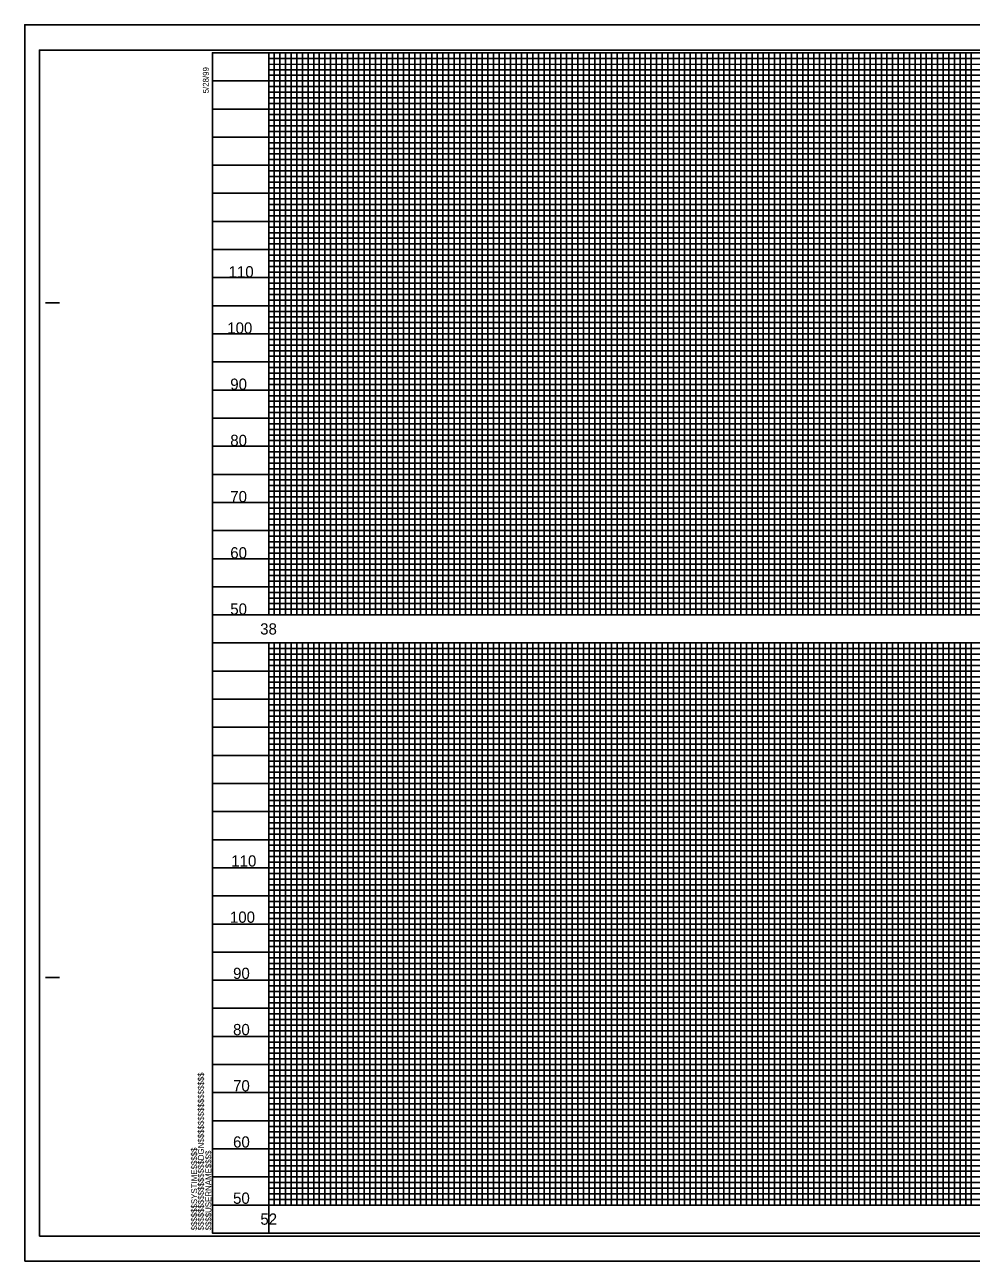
# Model space of a CAD drawing. Extents: x 2367101 to 2368930, y 803279 to 808979.
# Drawn here: x 2367101 to 2367943, y 803279 to 804379 of the extents above; entities that cross this region are included whole.
import ezdxf

# ---------------------------------------------------------------- set-up
doc = ezdxf.new("R2010")
doc.units = 0
for name, color, linetype in [('Old_Level_11', 7, 'Continuous'), ('Old_Level_12', 7, 'Continuous'), ('Old_Level_13', 7, 'Continuous'), ('Old_Level_14', 7, 'Continuous'), ('Old_Level_15', 7, 'Continuous'), ('Old_Level_17', 7, 'Continuous'), ('Old_Level_19', 7, 'Continuous'), ('Old_Level_4', 7, 'Continuous'), ('Old_Level_5', 7, 'Continuous'), ('Old_Level_6', 7, 'Continuous'), ('Old_Level_63', 7, 'Continuous'), ('Old_Level_8', 7, 'Continuous'), ('Old_Level_9', 7, 'Continuous')]:
    doc.layers.add(name, color=color, linetype=linetype)

msp = doc.modelspace()

# ---------------------------------------------------------------- linework, layer by layer
at = {"layer": 'Old_Level_11'}
for p, q in [((2367768, 803829), (2367818, 803829)), ((2367868, 803829), (2367918, 803829)), ((2367268, 803329), (2367268, 803329))]:
    msp.add_line(p, q, dxfattribs=at)
for points in [[(2367318, 804354), (2367318, 803854), (2367368, 803854), (2367368, 804354), (2367418, 804354), (2367418, 803854), (2367468, 803854), (2367468, 804354), (2367518, 804354), (2367518, 803854), (2367568, 803854), (2367568, 804354), (2367618, 804354), (2367618, 803854), (2367668, 803854), (2367668, 804354), (2367718, 804354), (2367718, 803854), (2367768, 803854), (2367768, 804354), (2367818, 804354), (2367818, 803854), (2367868, 803854), (2367868, 804354), (2367918, 804354), (2367918, 803854), (2367968, 803854)], [(2367268, 804304), (2368568, 804304)], [(2368568, 804254), (2367268, 804254), (2367268, 804204), (2368568, 804204)], [(2368768, 804154), (2367268, 804154), (2367268, 804104), (2368768, 804104)], [(2368768, 804054), (2367268, 804054), (2367268, 804004), (2368768, 804004)], [(2368768, 803954), (2367268, 803954), (2367268, 803954), (2367268, 803904), (2368768, 803904)], [(2367318, 803829), (2367318, 803329), (2367368, 803329), (2367368, 803829), (2367418, 803829), (2367418, 803329), (2367468, 803329), (2367468, 803829), (2367518, 803829), (2367518, 803329), (2367568, 803329), (2367568, 803829), (2367618, 803829), (2367618, 803329), (2367668, 803329), (2367668, 803829), (2367718, 803829), (2367718, 803329), (2367768, 803329), (2367768, 803829), (2367818, 803829), (2367818, 803329), (2367868, 803329), (2367868, 803829), (2367918, 803829), (2367918, 803329), (2367968, 803329)], [(2368768, 803779), (2367268, 803779)], [(2368768, 803729), (2367268, 803729), (2367268, 803679), (2368768, 803679)], [(2368768, 803629), (2367268, 803629), (2367268, 803579), (2368768, 803579)], [(2368768, 803529), (2367268, 803529), (2367268, 803479), (2368768, 803479)], [(2368768, 803429), (2367268, 803429), (2367268, 803429), (2367268, 803379), (2368768, 803379)], [(2368768, 803329), (2367268, 803329)]]:
    msp.add_lwpolyline(points, dxfattribs=at)
at = {"layer": 'Old_Level_12'}
msp.add_line((2367268, 804329), (2368567.9, 804329), dxfattribs=at)
for points in [[(2367343, 804354), (2367343, 803854), (2367393, 803854), (2367393, 804354), (2367443, 804354), (2367443, 803854), (2367493, 803854), (2367493, 804354), (2367543, 804354), (2367543, 803854), (2367593, 803854), (2367593, 804354), (2367643, 804354), (2367643, 803854), (2367693, 803854), (2367693, 804354), (2367743, 804354), (2367743, 803854), (2367793, 803854), (2367793, 804354), (2367843, 804354), (2367843, 803854), (2367893, 803854), (2367893, 803854), (2367893, 804354), (2367943, 804354), (2367943, 803854), (2367993, 803854)], [(2368568, 804279), (2367268, 804279), (2367268, 804229), (2368568, 804229)], [(2368768, 804179), (2367268, 804179), (2367268, 804129), (2368593, 804129)], [(2368768, 804079), (2367268, 804079), (2367268, 804029), (2368768, 804029)], [(2368768, 803979), (2367268, 803979), (2367268, 803929), (2368768, 803929)], [(2368768, 803879), (2367268, 803879)], [(2367293, 803829), (2367343, 803829), (2367343, 803329), (2367393, 803329), (2367393, 803829), (2367443, 803829), (2367443, 803329), (2367493, 803329), (2367493, 803829), (2367543, 803829), (2367543, 803329), (2367593, 803329), (2367593, 803829), (2367643, 803829), (2367643, 803329), (2367693, 803329), (2367693, 803829), (2367743, 803829), (2367743, 803329), (2367793, 803329), (2367793, 803829), (2367843, 803829), (2367843, 803329), (2367893, 803329), (2367893, 803329), (2367893, 803829), (2367943, 803829), (2367943, 803329), (2367993, 803329)], [(2367268, 803804), (2368768, 803804)], [(2368768, 803754), (2367268, 803754), (2367268, 803704), (2368768, 803704)], [(2368768, 803654), (2367268, 803654), (2367268, 803604), (2368768, 803604)], [(2368768, 803554), (2367268, 803554), (2367268, 803504), (2368768, 803504)], [(2368768, 803454), (2367268, 803454), (2367268, 803404), (2368768, 803404)], [(2368768, 803354), (2367268, 803354)]]:
    msp.add_lwpolyline(points, dxfattribs=at)
at = {"layer": 'Old_Level_13'}
for p, q in [((2367318, 803854), (2367318, 804354)), ((2367368, 803854), (2367368, 804354)), ((2367418, 803854), (2367418, 804354)), ((2367468, 803854), (2367468, 804354)), ((2367518, 803854), (2367518, 804354)), ((2367568, 803854), (2367568, 804354)), ((2367618, 803854), (2367618, 804354)), ((2367668, 803854), (2367668, 804354)), ((2367718, 803854), (2367718, 804354)), ((2367768, 803854), (2367768, 804354)), ((2367818, 803854), (2367818, 804354)), ((2367868, 803854), (2367868, 804354)), ((2367918, 803854), (2367918, 804354)), ((2368567.9, 804304), (2367268, 804304)), ((2368567.9, 804254), (2367268, 804254)), ((2368568, 804204), (2367268, 804204)), ((2368768, 804154), (2367268, 804154)), ((2368768, 804104), (2367268, 804104)), ((2368768, 804054), (2367268, 804054)), ((2368768, 804004), (2367268, 804004)), ((2368768, 803954), (2367268, 803954)), ((2368768, 803904), (2367268, 803904)), ((2367268, 803829), (2368767.9, 803829)), ((2367318, 803829), (2367318, 803329)), ((2367368, 803829), (2367368, 803329)), ((2367418, 803829), (2367418, 803329)), ((2367468, 803829), (2367468, 803329)), ((2367518, 803829), (2367518, 803329)), ((2367568, 803829), (2367568, 803329)), ((2367618, 803829), (2367618, 803329)), ((2367668, 803829), (2367668, 803329)), ((2367718, 803829), (2367718, 803329)), ((2367768, 803829), (2367768, 803329)), ((2367818, 803829), (2367818, 803329)), ((2367868, 803829), (2367868, 803329)), ((2367918, 803829), (2367918, 803329)), ((2367268, 803779), (2368767.9, 803779)), ((2367268, 803729), (2368767.9, 803729)), ((2367268, 803679), (2368767.9, 803679)), ((2367268, 803629), (2368767.9, 803629)), ((2367268, 803579), (2368767.9, 803579)), ((2367268, 803529), (2368767.9, 803529)), ((2367268, 803479), (2368767.9, 803479)), ((2367268, 803429), (2368767.9, 803429)), ((2367268, 803379), (2368767.9, 803379))]:
    msp.add_line(p, q, dxfattribs=at)
at = {"layer": 'Old_Level_14'}
msp.add_line((2367318, 803329), (2367318, 803304), dxfattribs=at)
at = {"layer": 'Old_Level_15'}
for p, q in [((2368785, 804379), (2367101, 804379)), ((2367101, 804379), (2367101, 803279)), ((2367101, 803279), (2368785, 803279))]:
    msp.add_line(p, q, dxfattribs=at)
at = {"layer": 'Old_Level_19'}
msp.add_line((2367268, 803904), (2367268, 803904), dxfattribs=at)
at = {"layer": 'Old_Level_4'}
msp.add_lwpolyline([(2367114, 803301.4), (2368780.5, 803301.4), (2368780.5, 804356.5), (2367114, 804356.5)], close=True, dxfattribs=at)
at = {"layer": 'Old_Level_5'}
msp.add_lwpolyline([(2367318, 803829), (2368718, 803829), (2368718, 803329), (2367318, 803329)], close=True, dxfattribs=at)
at = {"layer": 'Old_Level_6'}
msp.add_lwpolyline([(2367101, 803279), (2368785, 803279), (2368785, 804379), (2367101, 804379)], close=True, dxfattribs=at)
at = {"layer": 'Old_Level_63'}
msp.add_lwpolyline([(2367318, 804192.9), (2367318, 803854), (2368718, 803854), (2368718, 804192.9)], dxfattribs=at)
at = {"layer": 'Old_Level_8'}
for p, q in [((2367318, 804349), (2368568, 804349)), ((2367318, 804344), (2367318, 804344)), ((2368568, 804344), (2367318, 804343.6)), ((2367318, 804339), (2368568, 804339)), ((2368567.9, 804219), (2367318, 804219)), ((2368568, 804214), (2367318, 804214)), ((2368568, 804209), (2367318, 804209)), ((2367318, 804199), (2368568, 804199)), ((2368568, 804194), (2367318, 804194)), ((2367318, 804189), (2368718, 804189)), ((2368718, 804169), (2367318, 804169)), ((2367318, 804164), (2368718, 804164)), ((2368718, 804144), (2367318, 804144)), ((2367318, 804139), (2368718, 804139)), ((2368718, 804119), (2367318, 804119)), ((2367318, 804114), (2368718, 804114)), ((2368718, 804109), (2367318, 804109)), ((2367318, 804099), (2368718, 804099)), ((2368718, 804094), (2367318, 804094)), ((2367318, 804089), (2368718, 804089)), ((2368718, 804084), (2367318, 804084)), ((2367318, 804074), (2368718, 804074)), ((2368718, 804069), (2367318, 804069)), ((2367318, 804064), (2368718, 804064)), ((2368718, 804059), (2367318, 804059)), ((2367318, 804049), (2368718, 804049)), ((2368718, 804044), (2367318, 804044)), ((2367318, 804039), (2368718, 804039)), ((2368718, 804034), (2367318, 804034)), ((2367318, 804024), (2368718, 804024)), ((2368718, 804019), (2367318, 804019)), ((2367318, 804014), (2368718, 804014)), ((2368718, 804009), (2367318, 804009)), ((2367318, 803999), (2368718, 803999)), ((2368718, 803994), (2367318, 803994)), ((2367318, 803989), (2368718, 803989)), ((2368718, 803984), (2367318, 803984)), ((2367318, 803974), (2368718, 803974)), ((2368718, 803969), (2367318, 803969)), ((2368718, 803964), (2367318, 803964)), ((2368718, 803959), (2367318, 803959)), ((2367318, 803949), (2368718, 803949)), ((2368718, 803944), (2367318, 803944)), ((2367318, 803939), (2368718, 803939)), ((2368718, 803934), (2367318, 803934)), ((2367318, 803924), (2368718, 803924)), ((2368718, 803919), (2367318, 803919)), ((2367318, 803914), (2368718, 803914)), ((2368718, 803909), (2367318, 803909)), ((2367318, 803899), (2368718, 803899)), ((2368718, 803894), (2367318, 803894)), ((2367318, 803889), (2368718, 803889)), ((2368718, 803884), (2367318, 803884)), ((2367318, 803874), (2368718, 803874)), ((2368718, 803869), (2367318, 803869)), ((2367318, 803864), (2368718, 803864)), ((2367318, 803824), (2368718, 803824)), ((2368718, 803819), (2367318, 803819)), ((2367318, 803814), (2368718, 803814)), ((2368718, 803809), (2367318, 803809)), ((2367318, 803799), (2368718, 803799)), ((2368718, 803794), (2367318, 803794)), ((2367318, 803789), (2368718, 803789)), ((2368718, 803784), (2367318, 803784)), ((2367318, 803774), (2368718, 803774)), ((2368718, 803769), (2367318, 803769)), ((2367318, 803764), (2368718, 803764)), ((2368718, 803759), (2367318, 803759)), ((2367318, 803749), (2368718, 803749)), ((2368718, 803744), (2367318, 803744)), ((2367318, 803739), (2368718, 803739)), ((2368718, 803734), (2367318, 803734)), ((2367318, 803724), (2368718, 803724)), ((2368718, 803719), (2367318, 803719)), ((2367318, 803714), (2368718, 803714)), ((2368718, 803709), (2367318, 803709)), ((2367318, 803699), (2368718, 803699)), ((2368718, 803694), (2367318, 803694)), ((2367318, 803689), (2368718, 803689)), ((2368718, 803684), (2367318, 803684)), ((2367318, 803674), (2368718, 803674)), ((2368718, 803669), (2367318, 803669)), ((2367318, 803664), (2368718, 803664)), ((2368718, 803659), (2367318, 803659)), ((2367318, 803649), (2368718, 803649)), ((2368718, 803644), (2367318, 803644)), ((2367318, 803639), (2368718, 803639)), ((2368718, 803634), (2367318, 803634.1)), ((2367318, 803624), (2368718, 803624)), ((2368718, 803619), (2367318, 803619)), ((2367318, 803614), (2368718, 803614)), ((2368718, 803609), (2367318, 803609)), ((2367318, 803599), (2368718, 803599)), ((2368718, 803594), (2367318, 803594)), ((2367318, 803589), (2368718, 803589)), ((2368718, 803584), (2367318, 803584)), ((2367318, 803574), (2368718, 803574)), ((2368718, 803569), (2367318, 803569)), ((2367318, 803564), (2368718, 803564)), ((2368718, 803559), (2367318, 803559)), ((2367318, 803549), (2368718, 803549)), ((2368718, 803544), (2367318, 803544)), ((2367318, 803539), (2368718, 803539)), ((2368718, 803534), (2367318, 803534)), ((2367318, 803524), (2368718, 803524)), ((2368718, 803519), (2367318, 803519)), ((2367318, 803514), (2368718, 803514)), ((2368718, 803509), (2367318, 803509)), ((2367318, 803499), (2368718, 803499)), ((2368718, 803494), (2367318, 803494)), ((2367318, 803489), (2368718, 803489)), ((2368718, 803484), (2367318, 803484)), ((2367318, 803474), (2368718, 803474)), ((2368718, 803469), (2367318, 803469)), ((2367318, 803464), (2368718, 803464)), ((2368718, 803459), (2367318, 803459)), ((2367318, 803449), (2368718, 803449)), ((2368718, 803444), (2367318, 803444)), ((2367318, 803439), (2368718, 803439)), ((2368718, 803434), (2367318, 803434)), ((2367318, 803424), (2368718, 803424)), ((2368718, 803419), (2367318, 803419)), ((2367318, 803414), (2368718, 803414)), ((2368718, 803409), (2367318, 803409)), ((2367318, 803399), (2368718, 803399)), ((2368718, 803394), (2367318, 803394)), ((2367318, 803389), (2368718, 803389)), ((2368718, 803384), (2367318, 803384)), ((2367318, 803374), (2368718, 803374)), ((2368718, 803369), (2367318, 803369)), ((2367318, 803364), (2368718, 803364)), ((2368718, 803359), (2367318, 803359)), ((2367318, 803349), (2368718, 803349)), ((2368718, 803344), (2367318, 803344)), ((2367318, 803339), (2368718, 803339)), ((2367318, 803334), (2368718, 803334))]:
    msp.add_line(p, q, dxfattribs=at)
for points in [[(2367323, 804354), (2367323, 803854), (2367328, 803854), (2367328, 804354), (2367333, 804354), (2367333, 803854), (2367338, 803854), (2367338, 804354), (2367348, 804354), (2367348, 803854), (2367353, 803854), (2367353, 804354), (2367358, 804354), (2367358, 803854), (2367363, 803854), (2367373, 803854), (2367378, 803854), (2367378, 804354), (2367383, 804354), (2367383, 803854), (2367388, 803854), (2367388, 804354), (2367398, 804354), (2367398, 803854), (2367403, 803854), (2367403, 804354), (2367408, 804354), (2367408, 803854), (2367413, 803854), (2367413, 804354), (2367423, 804354), (2367423, 803854), (2367428, 803854), (2367428, 804354), (2367433, 804354), (2367433, 803854), (2367438, 803854), (2367438, 804354), (2367448, 804354), (2367448, 803854), (2367453, 803854), (2367453, 804354), (2367458, 804354), (2367458, 803854), (2367463, 803854), (2367463, 804354), (2367473, 804354), (2367473, 803854), (2367478, 803854), (2367478, 804354), (2367483, 804354), (2367483, 803854), (2367488, 803854), (2367488, 804354), (2367498, 804354), (2367498, 803854), (2367503, 803854), (2367503, 804354), (2367508, 804354), (2367508, 803854), (2367513, 803854), (2367513, 804354), (2367523, 804354), (2367523, 803854), (2367528, 803854), (2367528, 804354), (2367533, 804354), (2367533, 803854)], [(2367363, 803854), (2367363, 804354), (2367373, 804354), (2367373, 803854)], [(2367533, 803854), (2367538, 803854), (2367538, 804354), (2367548, 804354), (2367548, 803854), (2367553, 803854), (2367553, 804354), (2367558, 804354), (2367558, 803854), (2367563, 803854), (2367563, 804354), (2367573, 804354), (2367573, 803854), (2367578, 803854), (2367578, 804354), (2367583, 804354), (2367583, 803854), (2367588, 803854), (2367588, 804354), (2367598, 804354), (2367598, 803854), (2367603, 803854), (2367603, 804354), (2367608, 804354), (2367608, 803854), (2367613, 803854), (2367613, 804354), (2367623, 804354), (2367623, 803854), (2367628, 803854), (2367628, 804354), (2367633, 804354), (2367633, 803854), (2367638, 803854), (2367638, 804354), (2367648, 804354), (2367648, 803854), (2367653, 803854), (2367653, 804354), (2367658, 804354), (2367658, 803854), (2367663, 803854), (2367663, 804354), (2367673, 804354), (2367673, 803854), (2367678, 803854), (2367678, 804354), (2367683, 804354), (2367683, 803854), (2367688, 803854), (2367688, 804354), (2367698, 804354), (2367698, 803854), (2367703, 803854), (2367703, 804354), (2367708, 804354), (2367708, 803854), (2367713, 803854), (2367713, 804354), (2367723, 804354), (2367723, 803854), (2367728, 803854), (2367728, 804354), (2367733, 804354), (2367733, 803854), (2367738, 803854), (2367738, 804354), (2367748, 804354), (2367748, 803854), (2367753, 803854), (2367753, 804354), (2367758, 804354), (2367758, 803854), (2367763, 803854), (2367763, 804354), (2367773, 804354), (2367773, 803854), (2367778, 803854), (2367778, 804354), (2367783, 804354), (2367783, 803854), (2367788, 803854), (2367788, 804354), (2367798, 804354), (2367798, 803854), (2367803, 803854), (2367803, 804354), (2367808, 804354), (2367808, 803854), (2367813, 803854), (2367813, 804354), (2367823, 804354), (2367823, 803854), (2367828, 803854), (2367828, 804354), (2367833, 804354), (2367833, 803854), (2367838, 803854), (2367838, 804354), (2367848, 804354)], [(2367848, 804354), (2367848, 803854), (2367853, 803854), (2367853, 804354), (2367858, 804354), (2367858, 803854), (2367863, 803854), (2367863, 804354), (2367873, 804354), (2367873, 803854), (2367878, 803854), (2367878, 804354), (2367883, 804354), (2367883, 803854), (2367888, 803854), (2367888, 804354), (2367898, 804354), (2367898, 803854), (2367903, 803854), (2367903, 804354), (2367908, 804354), (2367908, 803854), (2367913, 803854), (2367913, 804354), (2367923, 804354), (2367923, 803854), (2367928, 803854), (2367928, 804354), (2367933, 804354), (2367933, 803854), (2367938, 803854), (2367938, 804354), (2367948, 804354)], [(2368568, 804334), (2367318, 804334), (2367318, 804324), (2368568, 804324)], [(2368567.9, 804319), (2367318, 804319), (2367318, 804314), (2368568, 804314)], [(2368568, 804309), (2367318, 804309), (2367318, 804299), (2368568, 804299)], [(2368568, 804294), (2367318, 804294), (2367318, 804289), (2368568, 804289)], [(2368568, 804284), (2367318, 804284), (2367318, 804274), (2368568, 804274)], [(2368568, 804269), (2367318, 804269), (2367318, 804264), (2368568, 804264)], [(2368568, 804259), (2367318, 804259), (2367318, 804249), (2368568, 804249)], [(2368568, 804243.9), (2367318.1, 804243.9), (2367318.1, 804239), (2368568, 804239)], [(2368568, 804234), (2367318, 804234), (2367318, 804224), (2368568, 804224)], [(2368718, 804184), (2367318, 804184), (2367318, 804174), (2368718, 804174)], [(2368718, 804159), (2367318, 804159), (2367318, 804149), (2368718, 804149)], [(2368718, 804134), (2367318, 804134), (2367318, 804124), (2368718, 804124)], [(2368718, 803859), (2367318, 803859)], [(2367318, 803829), (2367323, 803829), (2367323, 803329), (2367328, 803329), (2367328, 803829), (2367333, 803829), (2367333, 803329), (2367338, 803329), (2367338, 803829), (2367348, 803829), (2367348, 803329), (2367353, 803329), (2367353, 803829), (2367358, 803829), (2367358, 803329), (2367363, 803329), (2367373, 803329), (2367378, 803329), (2367378, 803829), (2367383, 803829), (2367383, 803329), (2367388, 803329), (2367388, 803829), (2367398, 803829), (2367398, 803329), (2367403, 803329), (2367403, 803829), (2367408, 803829), (2367408, 803329), (2367413, 803329), (2367413, 803829), (2367423, 803829), (2367423, 803329), (2367428, 803329), (2367428, 803829), (2367433, 803829), (2367433, 803329), (2367438, 803329), (2367438, 803829), (2367448, 803829), (2367448, 803329), (2367453, 803329), (2367453, 803829), (2367458, 803829), (2367458, 803329), (2367463, 803329), (2367463, 803829), (2367473, 803829), (2367473, 803329), (2367478, 803329), (2367478, 803829), (2367483, 803829), (2367483, 803329), (2367488, 803329), (2367488, 803829), (2367498, 803829), (2367498, 803329), (2367503, 803329), (2367503, 803829), (2367508, 803829), (2367508, 803329), (2367513, 803329), (2367513, 803829), (2367523, 803829), (2367523, 803329), (2367528, 803329), (2367528, 803829), (2367533, 803829), (2367533, 803329)], [(2367363, 803329), (2367363, 803829), (2367373, 803829), (2367373, 803329)], [(2367533, 803329), (2367538, 803329), (2367538, 803829), (2367548, 803829), (2367548, 803329), (2367553, 803329), (2367553, 803829), (2367558, 803829), (2367558, 803329), (2367563, 803329), (2367563, 803829), (2367573, 803829), (2367573, 803329), (2367578, 803329), (2367578, 803829), (2367583, 803829), (2367583, 803329), (2367588, 803329), (2367588, 803829), (2367598, 803829), (2367598, 803329), (2367603, 803329), (2367603, 803829), (2367608, 803829), (2367608, 803329), (2367613, 803329), (2367613, 803829), (2367623, 803829), (2367623, 803329), (2367628, 803329), (2367628, 803829), (2367633, 803829), (2367633, 803329), (2367638, 803329), (2367638, 803829), (2367648, 803829), (2367648, 803329), (2367653, 803329), (2367653, 803829), (2367658, 803829), (2367658, 803329), (2367663, 803329), (2367663, 803829), (2367673, 803829), (2367673, 803329), (2367678, 803329), (2367678, 803829), (2367683, 803829), (2367683, 803329), (2367688, 803329), (2367688, 803829), (2367698, 803829), (2367698, 803329), (2367703, 803329), (2367703, 803829), (2367708, 803829), (2367708, 803329), (2367713, 803329), (2367713, 803829), (2367723, 803829), (2367723, 803329), (2367728, 803329), (2367728, 803829), (2367733, 803829), (2367733, 803329), (2367738, 803329), (2367738, 803829), (2367748, 803829), (2367748, 803329), (2367753, 803329), (2367753, 803829), (2367758, 803829), (2367758, 803329), (2367763, 803329), (2367763, 803829), (2367773, 803829), (2367773, 803329), (2367778, 803329), (2367778, 803829), (2367783, 803829), (2367783, 803329), (2367788, 803329), (2367788, 803829), (2367798, 803829), (2367798, 803329), (2367803, 803329), (2367803, 803829), (2367808, 803829), (2367808, 803329), (2367813, 803329), (2367813, 803829), (2367823, 803829), (2367823, 803329), (2367828, 803329), (2367828, 803829), (2367833, 803829), (2367833, 803329), (2367838, 803329), (2367838, 803829), (2367848, 803829)], [(2367848, 803829), (2367848, 803329), (2367853, 803329), (2367853, 803829), (2367858, 803829), (2367858, 803329), (2367863, 803329), (2367863, 803829), (2367873, 803829), (2367873, 803329), (2367878, 803329), (2367878, 803829), (2367883, 803829), (2367883, 803329), (2367888, 803329), (2367888, 803829), (2367898, 803829), (2367898, 803329), (2367903, 803329), (2367903, 803829), (2367908, 803829), (2367908, 803329), (2367913, 803329), (2367913, 803829), (2367923, 803829), (2367923, 803329), (2367928, 803329), (2367928, 803829), (2367933, 803829), (2367933, 803329), (2367938, 803329), (2367938, 803829), (2367948, 803829)]]:
    msp.add_lwpolyline(points, dxfattribs=at)
at = {"layer": 'Old_Level_9'}
for p, q in [((2367119.5, 804131.5), (2367132, 804131.5)), ((2367268, 803854), (2368768, 803854)), ((2367268, 803829), (2368768, 803829)), ((2367119.5, 803531.5), (2367132, 803531.5)), ((2368768, 803329), (2367268, 803329)), ((2367268, 803304), (2368768, 803304)), ((2367268, 803304), (2367268, 803304)), ((2367268, 803304), (2367268, 803304)), ((2367268, 803304), (2367268, 803304)), ((2367268, 803304), (2367268, 803304)), ((2367268, 803304), (2367268, 803304)), ((2367268, 803304), (2367268, 803304)), ((2367268, 803304), (2367268, 803304))]:
    msp.add_line(p, q, dxfattribs=at)
msp.add_lwpolyline([(2368768, 804354), (2367268, 804354), (2367268, 803304), (2368768, 803304)], close=True, dxfattribs=at)
msp.add_lwpolyline([(2367305.5, 803304), (2367305.5, 803304)], dxfattribs=at)

# ---------------------------------------------------------------- texts
at = {"layer": 'Old_Level_17'}
for s, p in [('110', (2367282.3, 804154.2)), ('100', (2367281.1, 804104.2)), ('90', (2367283.8, 804054.2)), ('80', (2367283.8, 804004.2)), ('70', (2367283.8, 803954.2)), ('60', (2367283.8, 803904.2)), ('50', (2367283.8, 803854.2)), ('110', (2367284.7, 803630.1)), ('100', (2367283.5, 803580.1)), ('90', (2367286.3, 803530.1)), ('80', (2367286.3, 803480.1)), ('70', (2367286.3, 803430.1)), ('60', (2367286.3, 803380.1)), ('50', (2367286.3, 803330.1))]:
    msp.add_text(s, height=10, dxfattribs=at).set_placement(p)
at = {"layer": 'Old_Level_19'}
for s, p in [('38', (2367310.4, 803836.5)), ('52', (2367310.6, 803311.5))]:
    msp.add_text(s, height=10, dxfattribs=at).set_placement(p)
at = {"layer": 'Old_Level_9'}
for s, p in [('5/28/99', (2367264.7, 804317.9)), ('$$$$$$$$$$$$$$$$DGN$$$$$$$$$$$$$$$$', (2367260.3, 803306.4)), ('$$$$$$SYSTIME$$$$$', (2367254.3, 803306.4)), ('$$$$USERNAME$$$$', (2367266.9, 803306.4))]:
    msp.add_text(s, height=5.25, rotation=90, dxfattribs=at).set_placement(p)

doc.saveas('drawing.dxf')
